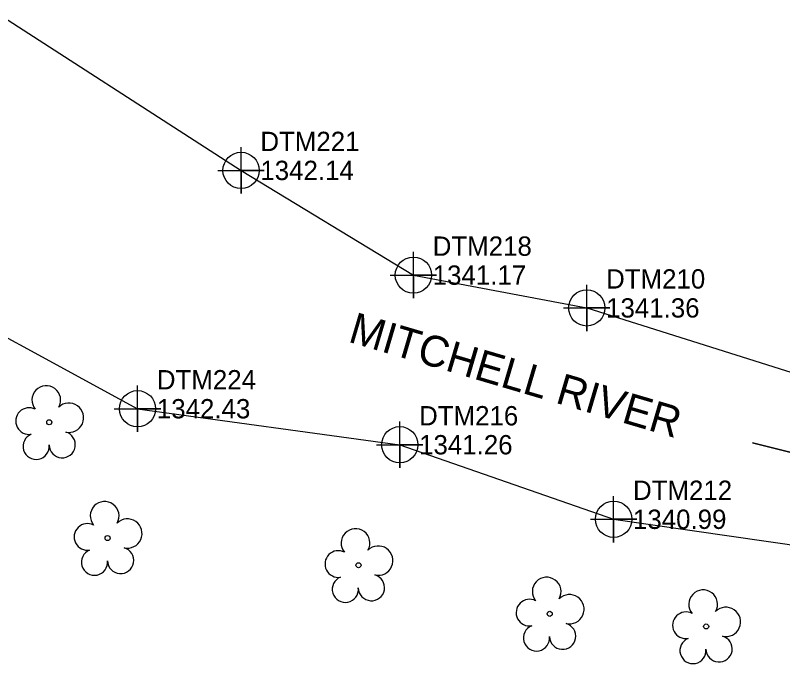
# Model space of a CAD drawing. Extents: x 1435573 to 1437263, y 981340 to 982884.
# Drawn here: x 1436236.5 to 1436335.7, y 982285.3 to 982369.2 of the extents above; entities that cross this region are included whole.
import ezdxf

# ---------------------------------------------------------------- set-up
doc = ezdxf.new("R2010")
doc.units = 0
for name, color, linetype in [('Exist Hydro Jurisdictional Stream or Body of Water', 7, 'Continuous'), ('Exist Hydro River Flow Arrow CELL', 7, 'Continuous'), ('Exist Hydro Stream or Body of Water Cogo Elevation', 7, 'Continuous'), ('Exist Hydro Stream or Body of Water Cogo Number', 7, 'Continuous'), ('Exist Hydro Stream or Body of Water Cogo Point CELL', 7, 'Continuous'), ('Exist Hydro Stream or Body of Water Text', 7, 'Continuous'), ('Exist Vegetation Tree CELL', 7, 'Continuous')]:
    doc.layers.add(name, color=color, linetype=linetype)

# ---------------------------------------------------------------- blocks, each defined once
blk = doc.blocks.new('EXIST HYDRO RIVER FLOW ARROW')
at = {"layer": 'Exist Hydro River Flow Arrow CELL'}
blk.add_line((0, 0), (0, 0), dxfattribs=at)
blk.add_lwpolyline([(0, 0.04575), (0.03775, 0.03), (0.07725, 0.01725), (0.118, 0.00775), (0.159, 0.0015), (0.2, 0), (-0.2, 0), (0.2, 0), (0.159, -0.0015), (0.118, -0.00775), (0.07725, -0.01725), (0.03775, -0.03), (0, -0.04575)], dxfattribs=at)

msp = doc.modelspace()

# ---------------------------------------------------------------- linework, layer by layer
at = {"layer": 'Exist Hydro Jurisdictional Stream or Body of Water'}
for points in [[(1436111.154, 982453.743), (1436137.021, 982423.293), (1436156.592, 982404.891), (1436183.389, 982389.762), (1436202.59, 982381.738), (1436230.764, 982371.657), (1436265.68, 982349.113), (1436287.963, 982335.567), (1436310.384, 982331.326), (1436342.495, 982321.193), (1436376.372, 982319.714), (1436409.657, 982315.499), (1436442.825, 982320.596), (1436463.486, 982320.372), (1436497.532, 982330.714), (1436550.332, 982336.593), (1436616.166, 982332.311)], [(1436091.982, 982443.751), (1436118.691, 982406.49), (1436146.126, 982381.568), (1436167.284, 982362.748), (1436182.899, 982351.8), (1436221.27, 982335.172), (1436252.295, 982318.284), (1436286.205, 982313.627), (1436313.861, 982303.985), (1436344.053, 982299.63), (1436382.914, 982293.643), (1436445.462, 982294.468), (1436493.305, 982296.219), (1436523.006, 982301.225), (1436526.678, 982304.851), (1436546.503, 982314.758), (1436602.72, 982314.242)]]:
    msp.add_lwpolyline(points, dxfattribs=at)
at = {"layer": 'Exist Hydro Stream or Body of Water Cogo Point CELL'}
for points in [[(1436262.68, 982349.113), (1436268.68, 982349.113), (1436265.68, 982349.113), (1436265.68, 982346.113), (1436265.68, 982352.113)], [(1436284.963, 982335.567), (1436290.963, 982335.567), (1436287.963, 982335.567), (1436287.963, 982332.567), (1436287.963, 982338.567)], [(1436307.384, 982331.326), (1436313.384, 982331.326), (1436310.384, 982331.326), (1436310.384, 982328.326), (1436310.384, 982334.326)], [(1436249.295, 982318.284), (1436255.295, 982318.284), (1436252.295, 982318.284), (1436252.295, 982315.284), (1436252.295, 982321.284)], [(1436283.205, 982313.627), (1436289.205, 982313.627), (1436286.205, 982313.627), (1436286.205, 982310.627), (1436286.205, 982316.627)], [(1436310.861, 982303.985), (1436316.861, 982303.985), (1436313.861, 982303.985), (1436313.861, 982300.985), (1436313.861, 982306.985)]]:
    msp.add_lwpolyline(points, dxfattribs=at)
for centre in [(1436265.68, 982349.113), (1436287.963, 982335.567), (1436310.384, 982331.326), (1436252.295, 982318.284), (1436286.205, 982313.627), (1436313.861, 982303.985)]:
    msp.add_circle(centre, 2.344, dxfattribs=at)
at = {"layer": 'Exist Vegetation Tree CELL'}
for p, q in [((1436240.882, 982316.531), (1436240.882, 982316.531)), ((1436248.431, 982301.552), (1436248.431, 982301.552)), ((1436280.869, 982298.042), (1436280.869, 982298.042)), ((1436305.588, 982291.753), (1436305.588, 982291.753)), ((1436325.82, 982290.117), (1436325.82, 982290.117))]:
    msp.add_line(p, q, dxfattribs=at)
for centre in [(1436240.882, 982316.531), (1436248.431, 982301.552), (1436280.869, 982298.042), (1436305.588, 982291.753), (1436325.82, 982290.117)]:
    msp.add_circle(centre, 0.326, dxfattribs=at)
for centre, radius, start, end in [((1436240.497, 982319.405), 1.856, 330.16508, 219.71335), ((1436243.431, 982317.12), 1.899, 257.1011, 134.19993), ((1436238.277, 982316.685), 1.727, 62.66361, 279.3457), ((1436239.178, 982313.41), 1.689, 111.56708, 6.23104), ((1436242.555, 982313.632), 1.698, 181.28216, 74.55999), ((1436248.046, 982304.425), 1.856, 330.16508, 219.71335), ((1436250.98, 982302.14), 1.899, 257.1011, 134.19993), ((1436245.826, 982301.706), 1.727, 62.66361, 279.3457), ((1436280.484, 982300.915), 1.856, 330.16508, 219.71335), ((1436246.727, 982298.431), 1.689, 111.56708, 6.23104), ((1436250.104, 982298.652), 1.698, 181.28216, 74.55999), ((1436278.264, 982298.195), 1.727, 62.66361, 279.3457), ((1436283.418, 982298.63), 1.899, 257.1011, 134.19993), ((1436279.165, 982294.921), 1.689, 111.56708, 6.23104), ((1436282.542, 982295.142), 1.698, 181.28216, 74.55999), ((1436305.203, 982294.627), 1.856, 330.16508, 219.71335), ((1436308.137, 982292.342), 1.899, 257.1011, 134.19993), ((1436325.435, 982292.991), 1.856, 330.16508, 219.71335), ((1436302.982, 982291.907), 1.727, 62.66361, 279.3457), ((1436323.214, 982290.271), 1.727, 62.66361, 279.3457), ((1436328.369, 982290.706), 1.899, 257.1011, 134.19993), ((1436303.884, 982288.633), 1.689, 111.56708, 6.23104), ((1436307.261, 982288.854), 1.698, 181.28216, 74.55999), ((1436324.116, 982286.997), 1.689, 111.56708, 6.23104), ((1436327.493, 982287.218), 1.698, 181.28216, 74.55999)]:
    msp.add_arc(centre, radius, start, end, dxfattribs=at)

# ---------------------------------------------------------------- block references
at = {"layer": 'Exist Hydro River Flow Arrow CELL', "xscale": 49.99999999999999, "yscale": 50, "rotation": -14.136022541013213}
msp.add_blockref('EXIST HYDRO RIVER FLOW ARROW', (1436341.491, 982311.428), dxfattribs=at)

# ---------------------------------------------------------------- texts
at = {"layer": 'Exist Hydro Stream or Body of Water Cogo Elevation'}
for s, p in [('1342.14', (1436268.18, 982347.863)), ('1341.17', (1436290.463, 982334.318)), ('1341.36', (1436312.884, 982330.076)), ('1342.43', (1436254.795, 982317.034)), ('1341.26', (1436288.705, 982312.377)), ('1340.99', (1436316.361, 982302.735))]:
    msp.add_text(s, height=2.5, dxfattribs=at).set_placement(p)
at = {"layer": 'Exist Hydro Stream or Body of Water Cogo Number'}
for s, p in [('DTM221', (1436268.18, 982351.613)), ('DTM218', (1436290.463, 982338.068)), ('DTM210', (1436312.884, 982333.826)), ('DTM224', (1436254.795, 982320.784)), ('DTM216', (1436288.705, 982316.127)), ('DTM212', (1436316.361, 982306.485))]:
    msp.add_text(s, height=2.5, dxfattribs=at).set_placement(p)
at = {"layer": 'Exist Hydro Stream or Body of Water Text'}
msp.add_text('MITCHELL RIVER', height=4, rotation=343.58547, dxfattribs=at).set_placement((1436279.395, 982326.979))

doc.saveas('drawing.dxf')
